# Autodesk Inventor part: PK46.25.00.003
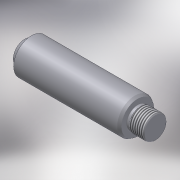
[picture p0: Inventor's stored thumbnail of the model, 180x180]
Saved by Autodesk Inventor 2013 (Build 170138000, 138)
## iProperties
Created: 2005-05
Part Number: PK46.25.00.003
Material: Steel, Mild
Document SubType Name: Modeling
Designer: PVitaliy
Manufacturer: Standard
Standards Organization: Custom
Density: 7.86 g/cm^3
Author: PVitaliy
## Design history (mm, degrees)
sketch "Эскиз2"
  geometry: L1 (0, 0)-(95.139, 0); L2 (0, 0)-(0, 25.897); L3 (0, 25.897)-(13, 35); L4 (13, 35)-(15, 35); L5 (15, 35)-(15, 40); L6 (15, 40)-(249, 40); L7 (249, 40)-(255, 36.536); L8 (255, 36.536)-(255, 24.5); L9 (255, 24.5)-(261, 24.5); L10 (261, 24.5)-(262.5, 26); L11 (262.5, 26)-(295, 26); L12 (295, 26)-(295, 0); L13 (295, 0)-(0, 0)
  constraints: 26 end point, 6 horizontal, 4 vertical, 1 other
  dimensions: "d0" = 70 diameter of L4 L1; "d1" = 35 deg angle of L3 L4; "d2" = 15 distance between parallel lines of L5 L2; "d3" = 2 distance of L3.end L4.end; "d4" = 80 diameter of L6 L1; "d5" = 240 distance between parallel lines of L8 L5; "d6" = 30 deg angle of L6 L7; "d7" = 6 horizontal distance of L6.end L7.end; "d8" = 295 distance between parallel lines of L12 L2; "d9" = 52 diameter of L11 L1; "d10" = 6 distance of L8.end L9.end; "d11" = 49 diameter of L9 L1; "d12" = 45 deg angle of L10 L9
revolve "Вращение1" sketch "Эскиз2" stored, may be unused: angle "d13" = 90 deg
feature "Резьба1" dims "d14" = 10, "d15" = 0
chamfer "Фаска1" distance "d16" = 1.6; stored, may be unused: second distance "d17" = 2, angle "d18" = 45 deg
fillet "Сопряжение1" dims "d19" = 1, "d20" = 0.5
body "Solid1"
